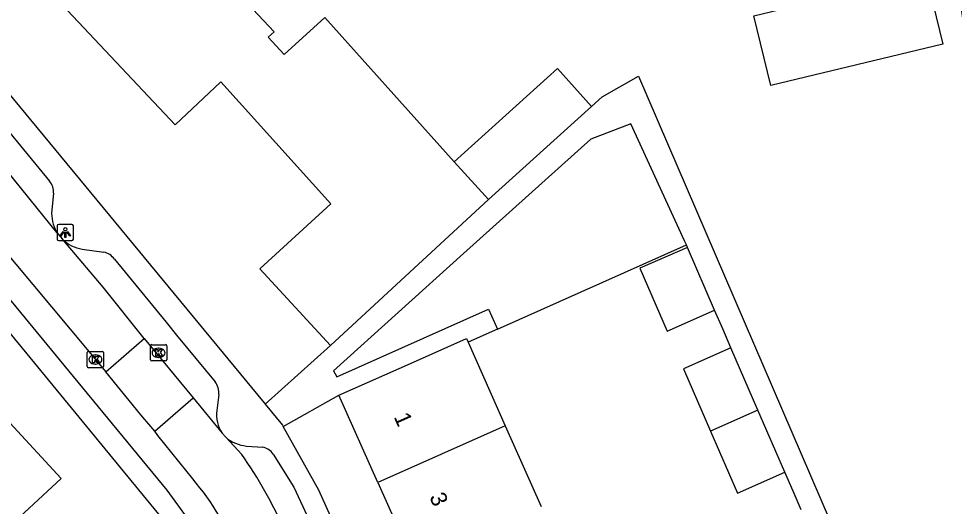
# Model space of a CAD drawing. Extents: x 163150 to 163546, y 380933 to 381635.
# Drawn here: x 163251.7 to 163309.2, y 381223.2 to 381253.2 of the extents above; entities that cross this region are included whole.
import ezdxf

# ---------------------------------------------------------------- set-up
doc = ezdxf.new("R2010")
doc.units = 0
for name, color, linetype in [('IMGEO_Erf', 7, 'Continuous'), ('IMGEO_Kolk', 7, 'Continuous'), ('IMGEO_Lichtpunt', 7, 'Continuous'), ('IMGEO_Pand', 7, 'Continuous'), ('IMGEO_Pand_nummerreeks', 7, 'Continuous'), ('IMGEO_Rijbaan_lokaal_open', 7, 'Continuous'), ('IMGEO_Voetpad_open', 7, 'Continuous')]:
    doc.layers.add(name, color=color, linetype=linetype)

msp = doc.modelspace()

# ---------------------------------------------------------------- linework, layer by layer
at = {"layer": 'IMGEO_Erf'}
msp.add_lwpolyline([(163281.127, 381234.095), (163292.732, 381239.262)], dxfattribs=at)
at = {"layer": 'IMGEO_Kolk'}
for p, q in [((163259.808, 381232.209), (163259.808, 381233.061)), ((163259.883, 381233.135), (163260.735, 381233.135)), ((163260.809, 381233.061), (163260.809, 381232.209)), ((163255.924, 381231.795), (163255.924, 381232.647)), ((163255.999, 381232.721), (163256.851, 381232.721)), ((163256.412, 381232.501), (163256.437, 381232.501)), ((163256.925, 381232.647), (163256.925, 381231.795)), ((163260.296, 381232.915), (163260.321, 381232.915)), ((163256.435, 381231.941), (163256.41, 381231.941)), ((163260.735, 381232.135), (163259.883, 381232.135)), ((163260.319, 381232.355), (163260.294, 381232.355)), ((163256.851, 381231.721), (163255.999, 381231.721))]:
    msp.add_line(p, q, dxfattribs=at)
for points in [[(163259.808, 381232.209), (163259.808, 381233.061)], [(163259.883, 381233.135), (163260.735, 381233.135)], [(163260.809, 381233.061), (163260.809, 381232.209)], [(163255.924, 381231.795), (163255.924, 381232.647)], [(163255.999, 381232.721), (163256.851, 381232.721)], [(163256.245, 381232.421), (163256.368, 381232.421), (163256.368, 381232.27), (163256.498, 381232.421), (163256.662, 381232.421), (163256.516, 381232.27), (163256.669, 381232.021), (163256.517, 381232.021), (163256.432, 381232.185), (163256.368, 381232.118), (163256.368, 381232.021), (163256.245, 381232.021), (163256.245, 381232.421)], [(163256.925, 381232.647), (163256.925, 381231.795)], [(163260.129, 381232.835), (163260.252, 381232.835), (163260.252, 381232.684), (163260.382, 381232.835), (163260.546, 381232.835), (163260.4, 381232.684), (163260.553, 381232.435), (163260.401, 381232.435), (163260.316, 381232.599), (163260.252, 381232.532), (163260.252, 381232.435), (163260.129, 381232.435), (163260.129, 381232.835)], [(163260.735, 381232.135), (163259.883, 381232.135)], [(163256.851, 381231.721), (163255.999, 381231.721)]]:
    msp.add_lwpolyline(points, dxfattribs=at)
for centre, start, end in [((163259.885, 381233.059), 91.55205, 178.44795), ((163259.885, 381233.059), 91.55205, 178.44795), ((163260.733, 381233.059), 1.55205, 88.44795), ((163260.733, 381233.059), 1.55205, 88.44795), ((163256.001, 381232.645), 91.55205, 178.44795), ((163256.001, 381232.645), 91.55205, 178.44795), ((163256.849, 381232.645), 1.55205, 88.44795), ((163256.849, 381232.645), 1.55205, 88.44795), ((163259.885, 381232.211), 181.55205, 268.44795), ((163259.885, 381232.211), 181.55205, 268.44795), ((163260.733, 381232.211), 271.55205, 358.44795), ((163260.733, 381232.211), 271.55205, 358.44795), ((163256.001, 381231.797), 181.55205, 268.44795), ((163256.001, 381231.797), 181.55205, 268.44795), ((163256.849, 381231.797), 271.55205, 358.44795), ((163256.849, 381231.797), 271.55205, 358.44795)]:
    msp.add_arc(centre, 0.0765, start, end, dxfattribs=at)
for centre, major_axis, ratio, start_param, end_param in [((163256.411, 381232.221), (-0.387, 0.002), 0.722429, 4.712389, 7.853982), ((163256.436, 381232.221), (-0.39, 0.002), 0.717154, 1.570796, 4.712389), ((163260.295, 381232.635), (-0.387, 0.002), 0.722429, 4.712389, 7.853982), ((163260.32, 381232.635), (-0.39, 0.002), 0.717154, 1.570796, 4.712389)]:
    msp.add_ellipse(centre, major_axis=major_axis, ratio=ratio, start_param=start_param, end_param=end_param, dxfattribs=at)
at = {"layer": 'IMGEO_Lichtpunt'}
for p, q in [((163254.98, 381240.521), (163254.172, 381240.521)), ((163254.98, 381240.521), (163254.172, 381240.521)), ((163254.078, 381240.426), (163254.078, 381239.619)), ((163254.078, 381240.426), (163254.078, 381239.619)), ((163255.074, 381239.619), (163255.074, 381240.426)), ((163255.074, 381239.619), (163255.074, 381240.426)), ((163254.172, 381239.525), (163254.98, 381239.525)), ((163254.172, 381239.525), (163254.98, 381239.525))]:
    msp.add_line(p, q, dxfattribs=at)
for points in [[(163254.452, 381240.09), (163254.491, 381240.062), (163254.303, 381239.8), (163254.265, 381239.827), (163254.452, 381240.09)], [(163254.554, 381240.042), (163254.601, 381240.042), (163254.601, 381239.72), (163254.554, 381239.72), (163254.554, 381240.042)], [(163254.664, 381240.062), (163254.702, 381240.089), (163254.889, 381239.827), (163254.85, 381239.799), (163254.664, 381240.062)]]:
    msp.add_lwpolyline(points, dxfattribs=at)
msp.add_circle((163254.577, 381240.224), 0.0994, dxfattribs=at)
for centre, start, end in [((163254.172, 381240.426), 90, 180), ((163254.172, 381240.426), 90, 180), ((163254.98, 381240.426), 0, 90), ((163254.98, 381240.426), 0, 90), ((163254.172, 381239.619), 180, 270), ((163254.172, 381239.619), 180, 270), ((163254.98, 381239.619), 270, 0), ((163254.98, 381239.619), 270, 360)]:
    msp.add_arc(centre, 0.0946, start, end, dxfattribs=at)
at = {"layer": 'IMGEO_Pand'}
for points in [[(163270.859, 381233.088), (163266.522, 381237.793), (163270.892, 381241.794), (163264.13, 381249.279), (163261.324, 381246.64), (163254.056, 381254.37), (163260.133, 381260.084), (163267.4, 381252.354), (163267.219, 381252.189), (163267.042, 381252.027), (163267.537, 381251.485), (163268.019, 381250.956), (163270.516, 381253.234), (163278.474, 381244.372)], [(163307.445, 381255.9), (163308.483, 381251.605), (163297.911, 381249.049), (163296.872, 381253.344), (163307.445, 381255.9)], [(163278.474, 381244.372), (163284.814, 381250.091), (163286.908, 381247.77)], [(163286.908, 381247.77), (163280.568, 381242.051)], [(163280.568, 381242.051), (163278.474, 381244.372)], [(163280.568, 381242.051), (163270.859, 381233.088)], [(163292.803, 381239.099), (163289.881, 381237.834), (163291.554, 381233.97), (163294.464, 381235.263)], [(163294.464, 381235.263), (163292.803, 381239.099)], [(163271.388, 381230.039), (163275.957, 381232.07), (163279.22, 381233.521), (163279.322, 381233.291)], [(163279.322, 381233.291), (163281.602, 381228.156)], [(163295.466, 381232.949), (163292.556, 381231.656), (163294.215, 381227.826)], [(163297.124, 381229.12), (163295.466, 381232.949)], [(163273.773, 381224.674), (163271.388, 381230.039)], [(163297.124, 381229.12), (163294.215, 381227.826)], [(163298.776, 381225.305), (163297.124, 381229.12)], [(163250.677, 381228.873), (163254.325, 381224.911), (163250.648, 381221.524), (163247.986, 381219.073), (163245.994, 381221.236), (163243.775, 381219.218), (163243.555, 381219.018), (163241.872, 381220.867)], [(163281.602, 381228.156), (163273.773, 381224.674)], [(163281.602, 381228.156), (163283.805, 381223.195)], [(163294.215, 381227.826), (163295.867, 381224.011), (163298.776, 381225.305)], [(163273.773, 381224.674), (163275.979, 381219.714)]]:
    msp.add_lwpolyline(points, dxfattribs=at)
at = {"layer": 'IMGEO_Rijbaan_lokaal_open'}
for points in [[(163254.133, 381239.93), (163247.344, 381248.323)], [(163244.845, 381246.068), (163257.059, 381231.46)], [(163254.133, 381239.93), (163254.406, 381239.609)], [(163259.423, 381233.518), (163256.909, 381236.671), (163254.406, 381239.609)], [(163257.059, 381231.46), (163259.423, 381233.518)], [(163259.423, 381233.518), (163262.433, 381229.864)], [(163260.079, 381227.819), (163259.221, 381228.826), (163257.059, 381231.46)], [(163260.079, 381227.819), (163260.411, 381228.106), (163262.433, 381229.864)], [(163262.433, 381229.864), (163264.216, 381227.699)], [(163262.401, 381224.889), (163260.269, 381227.564), (163260.079, 381227.819)], [(163264.216, 381227.699), (163264.429, 381227.449)], [(163265.412, 381226.393), (163264.429, 381227.449)]]:
    msp.add_lwpolyline(points, dxfattribs=at)
for centre, radius, start, end in [((163245.599, 381212.256), 24.34, 22.94332, 35.50854), ((163249.024, 381213.537), 17.545, 21.99232, 40.31853)]:
    msp.add_arc(centre, radius, start, end, dxfattribs=at)
at = {"layer": 'IMGEO_Voetpad_open'}
for points in [[(163286.908, 381247.77), (163287.555, 381248.354), (163289.781, 381249.639), (163311.555, 381199.092), (163317.049, 381199.939), (163308.6, 381261.231), (163298.145, 381259.806)], [(163247.371, 381253.054), (163249.895, 381250), (163266.785, 381229.563), (163266.853, 381229.481)], [(163250.029, 381247.52), (163253.614, 381243.176)], [(163282.659, 381139.767), (163292.918, 381150.971), (163261.531, 381220.959), (163260.513, 381222.504), (163240.64, 381246.663)], [(163292.732, 381239.262), (163292.625, 381239.51), (163289.321, 381246.708), (163286.852, 381245.76), (163279.044, 381238.73), (163271.048, 381231.531), (163271.253, 381231.167), (163280.578, 381235.316), (163281.127, 381234.095)], [(163262.732, 381221.585), (163260.84, 381224.198), (163255.077, 381231.183), (163245.546, 381242.743), (163245.181, 381243.186)], [(163253.851, 381242.433), (163253.735, 381241.201)], [(163255.617, 381239.008), (163256.938, 381238.814)], [(163292.803, 381239.099), (163292.732, 381239.262)], [(163257.592, 381238.38), (163260.764, 381234.508), (163261.405, 381233.726), (163263.78, 381230.855)], [(163295.466, 381232.949), (163294.967, 381234.1), (163294.464, 381235.263)], [(163281.127, 381234.095), (163279.322, 381233.291)], [(163266.853, 381229.481), (163270.859, 381233.088)], [(163264.009, 381230.078), (163263.886, 381229.082)], [(163267.96, 381228.115), (163271.388, 381230.039)], [(163266.853, 381229.481), (163267.915, 381228.196), (163267.96, 381228.115)], [(163304.985, 381145.89), (163305.202, 381146.131), (163270.156, 381224.203), (163267.96, 381228.115)], [(163265.707, 381226.909), (163266.704, 381226.832)], [(163267.348, 381226.416), (163268.608, 381224.383), (163270.262, 381220.868), (163272.353, 381216.176), (163279.471, 381200.146)], [(163299.776, 381222.996), (163299.281, 381224.139), (163298.776, 381225.305)]]:
    msp.add_lwpolyline(points, dxfattribs=at)
for centre, radius, start, end in [((163252.843, 381242.521), 1.012, 355.03496, 40.34803), ((163255.947, 381241.196), 2.212, 179.86384, 214.91093), ((163255.948, 381241.196), 2.213, 225.82018, 261.39087), ((163256.765, 381237.844), 0.985, 32.95622, 79.9066), ((163262.921, 381230.18), 1.093, 354.66866, 38.17428), ((163265.754, 381228.797), 1.889, 171.31658, 215.52442), ((163265.916, 381229.186), 2.286, 229.42989, 264.75858), ((163266.506, 381225.819), 1.033, 35.34937, 78.92873)]:
    msp.add_arc(centre, radius, start, end, dxfattribs=at)

# ---------------------------------------------------------------- texts
at = {"layer": 'IMGEO_Pand_nummerreeks'}
for s, rotation, p in [('1', 293.97234, (163274.741, 381228.701)), ('3', 293.97147, (163276.924, 381223.788))]:
    msp.add_text(s, height=1, rotation=rotation, dxfattribs=at).set_placement(p)

doc.saveas('drawing.dxf')
